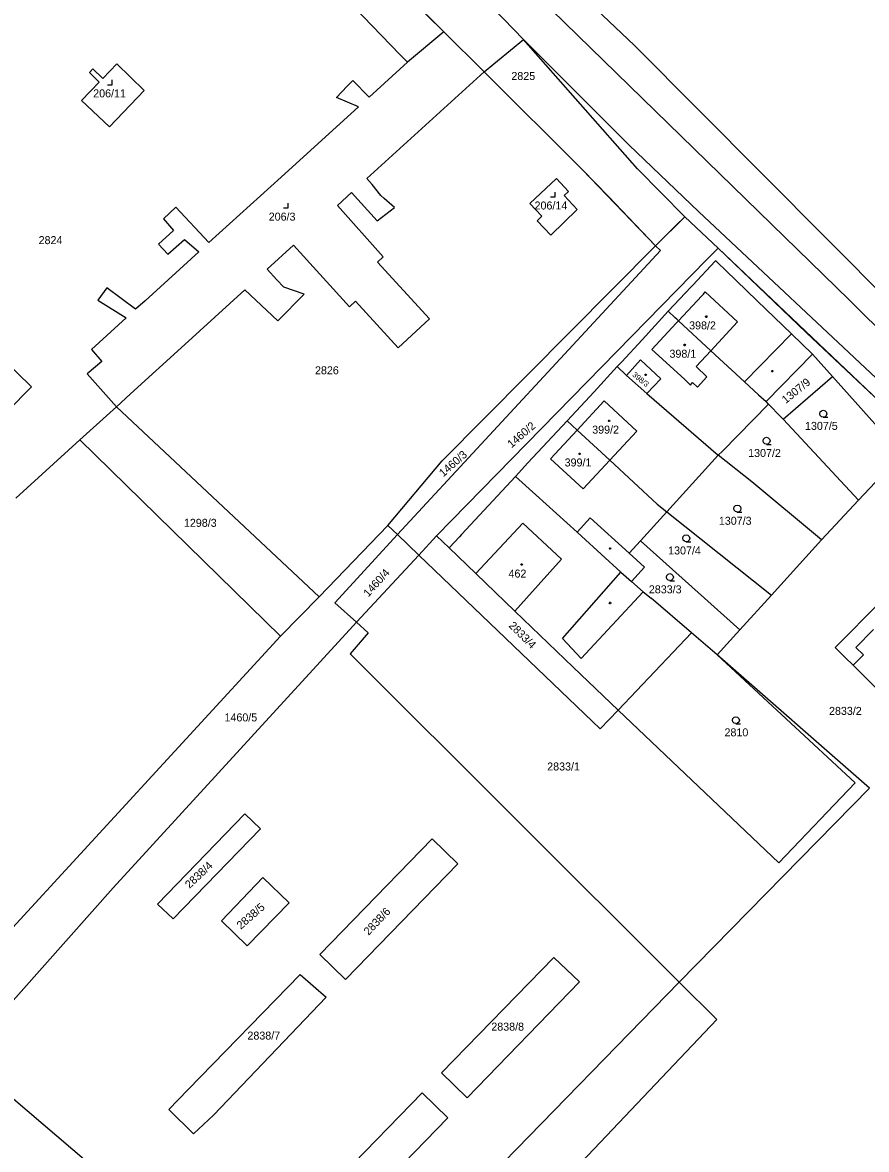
# Model space of a CAD drawing. Extents: x -580630 to -576196, y -1189024 to -1183567.
# Drawn here: x -577874.8 to -577695.4, y -1187048.7 to -1186809.3 of the extents above; entities that cross this region are included whole.
import ezdxf

# ---------------------------------------------------------------- set-up
doc = ezdxf.new("R2010")
doc.units = 0
for name, color, linetype in [('Vrstva 1', 7, 'Continuous'), ('Vrstva 18', 7, 'Continuous'), ('Vrstva 19', 7, 'Continuous'), ('Vrstva 25', 7, 'Continuous'), ('Vrstva 4', 7, 'Continuous'), ('Vrstva 63', 7, 'Continuous')]:
    doc.layers.add(name, color=color, linetype=linetype)

msp = doc.modelspace()

# ---------------------------------------------------------------- linework, layer by layer
at = {"layer": 'Vrstva 1'}
for p, q in [((-577782.94, -1186777.73), (-577744.75, -1186814.09)), ((-577800.81, -1186795.8), (-577785.23, -1186811.22)), ((-577768.28, -1186812.86), (-577782.75, -1186797.76)), ((-577807.36, -1186802.79), (-577794.61, -1186816.06)), ((-577785.23, -1186811.22), (-577792.94, -1186817.71)), ((-577785.23, -1186811.22), (-577776.66, -1186819.72)), ((-577773.84, -1186817.41), (-577768.28, -1186812.86)), ((-577744.05, -1186840.37), (-577768.28, -1186812.86)), ((-577794.61, -1186816.06), (-577792.94, -1186817.71)), ((-577744.75, -1186814.09), (-577644.5, -1186914.93)), ((-577854.75, -1186818.07), (-577857.71, -1186821.15)), ((-577848.88, -1186823.72), (-577854.75, -1186818.07)), ((-577792.94, -1186817.71), (-577801.12, -1186825.14)), ((-577776.66, -1186819.72), (-577774.63, -1186818.06)), ((-577774.63, -1186818.06), (-577773.84, -1186817.41)), ((-577859.82, -1186819.14), (-577860.55, -1186819.89)), ((-577860.55, -1186819.89), (-577858.49, -1186821.96)), ((-577857.71, -1186821.15), (-577859.82, -1186819.14)), ((-577801.58, -1186842.42), (-577776.66, -1186819.72)), ((-577755.77, -1186840.55), (-577776.66, -1186819.72)), ((-577858.49, -1186821.96), (-577862.22, -1186825.84)), ((-577808.07, -1186825.19), (-577805.79, -1186822.78)), ((-577805.79, -1186822.78), (-577804.55, -1186821.56)), ((-577804.55, -1186821.56), (-577801.12, -1186825.14)), ((-577856.29, -1186831.45), (-577848.88, -1186823.72)), ((-577803.35, -1186827.16), (-577808.07, -1186825.19)), ((-577862.22, -1186825.84), (-577856.29, -1186831.45)), ((-577803.35, -1186827.16), (-577819.81, -1186842.11)), ((-577819.81, -1186842.11), (-577835.15, -1186856.03)), ((-577800.48, -1186843.65), (-577801.58, -1186842.42)), ((-577766.94, -1186847.71), (-577761.3, -1186842.44)), ((-577761.3, -1186842.44), (-577758.76, -1186845.16)), ((-577750.21, -1186846.26), (-577755.77, -1186840.55)), ((-577734, -1186850.52), (-577744.05, -1186840.37)), ((-577798.63, -1186846.02), (-577800.48, -1186843.65)), ((-577807.85, -1186848.13), (-577804.85, -1186845.4)), ((-577804.85, -1186845.4), (-577799.37, -1186851.42)), ((-577797.93, -1186846.68), (-577798.63, -1186846.02)), ((-577795.74, -1186848.59), (-577797.93, -1186846.68)), ((-577758.76, -1186845.16), (-577759.62, -1186846.03)), ((-577759.62, -1186846.03), (-577756.86, -1186848.97)), ((-577740.21, -1186856.7), (-577750.21, -1186846.26)), ((-577842.17, -1186848.48), (-577844.84, -1186851)), ((-577835.15, -1186856.03), (-577842.17, -1186848.48)), ((-577798.1, -1186859.02), (-577807.85, -1186848.13)), ((-577799.37, -1186851.42), (-577795.74, -1186848.59)), ((-577764.38, -1186850.44), (-577766.94, -1186847.71)), ((-577756.86, -1186848.97), (-577762.49, -1186854.48)), ((-577844.84, -1186851), (-577842.65, -1186853.47)), ((-577765.42, -1186851.41), (-577764.38, -1186850.44)), ((-577762.49, -1186854.48), (-577765.42, -1186851.41)), ((-577735.9, -1186852.41), (-577734, -1186850.52)), ((-577734, -1186850.52), (-577726.95, -1186857.21)), ((-577842.65, -1186853.47), (-577845.86, -1186856.35)), ((-577740.21, -1186856.7), (-577736.61, -1186853.12)), ((-577736.61, -1186853.12), (-577735.9, -1186852.41)), ((-577845.86, -1186856.35), (-577843.91, -1186858.47)), ((-577843.91, -1186858.47), (-577840.36, -1186855.34)), ((-577840.36, -1186855.34), (-577837.27, -1186857.96)), ((-577822.77, -1186861.7), (-577817.15, -1186856.59)), ((-577817.15, -1186856.59), (-577805.3, -1186869.66)), ((-577785.58, -1186902.38), (-577740.21, -1186856.7)), ((-577739.17, -1186857.68), (-577740.21, -1186856.7)), ((-577837.27, -1186857.96), (-577848.7, -1186868.38)), ((-577799.34, -1186860.18), (-577798.1, -1186859.02)), ((-577795.04, -1186918.08), (-577739.17, -1186857.68)), ((-577729.3, -1186859.62), (-577728.55, -1186858.85)), ((-577728.55, -1186858.85), (-577726.95, -1186857.21)), ((-577726.95, -1186857.21), (-577691.26, -1186891.06)), ((-577788.27, -1186872.25), (-577799.34, -1186860.18)), ((-577786.79, -1186918.33), (-577729.3, -1186859.62)), ((-577727.54, -1186859.97), (-577732.3, -1186865.05)), ((-577727.45, -1186859.87), (-577727.54, -1186859.97)), ((-577727.08, -1186860.23), (-577727.45, -1186859.87)), ((-577725.29, -1186861.95), (-577727.08, -1186860.23)), ((-577820.71, -1186863.94), (-577822.77, -1186861.7)), ((-577819.25, -1186865.53), (-577820.71, -1186863.94)), ((-577718.61, -1186868.4), (-577725.29, -1186861.95)), ((-577856.87, -1186865.61), (-577858.79, -1186868.26)), ((-577850.77, -1186870.2), (-577856.87, -1186865.61)), ((-577840.3, -1186877.65), (-577827.54, -1186866.04)), ((-577827.54, -1186866.04), (-577820.51, -1186872.68)), ((-577814.9, -1186866.97), (-577819.25, -1186865.53)), ((-577732.65, -1186865.42), (-577737.52, -1186870.62)), ((-577732.3, -1186865.05), (-577732.65, -1186865.42)), ((-577858.79, -1186868.26), (-577852.77, -1186872.04)), ((-577848.7, -1186868.38), (-577850.77, -1186870.2)), ((-577820.51, -1186872.68), (-577814.9, -1186866.97)), ((-577805.3, -1186869.66), (-577803.99, -1186868.47)), ((-577803.99, -1186868.47), (-577794.9, -1186878.4)), ((-577711.33, -1186875.42), (-577718.61, -1186868.4)), ((-577737.52, -1186870.62), (-577743.11, -1186876.67)), ((-577736.06, -1186871.98), (-577737.52, -1186870.62)), ((-577852.77, -1186872.04), (-577860.12, -1186878.72)), ((-577794.9, -1186878.4), (-577788.27, -1186872.25)), ((-577735.69, -1186872.32), (-577736.06, -1186871.98)), ((-577735.36, -1186872.63), (-577735.69, -1186872.32)), ((-577728.47, -1186879), (-577735.36, -1186872.63)), ((-577711.33, -1186875.42), (-577706.86, -1186879.71)), ((-577851.82, -1186888.13), (-577840.3, -1186877.65)), ((-577743.11, -1186876.67), (-577747.42, -1186881.36)), ((-577872.83, -1186886.7), (-577879.18, -1186880.49)), ((-577860.12, -1186878.72), (-577857.88, -1186881.26)), ((-577728.47, -1186879), (-577721.32, -1186885.59)), ((-577706.86, -1186879.71), (-577716.71, -1186889.82)), ((-577702.59, -1186884.51), (-577706.86, -1186879.71)), ((-577857.88, -1186881.26), (-577861.01, -1186883.91)), ((-577753.25, -1186887.71), (-577748.4, -1186882.35)), ((-577747.42, -1186881.36), (-577748.4, -1186882.35)), ((-577748.4, -1186882.35), (-577746.43, -1186884.23)), ((-577746.43, -1186884.23), (-577743.44, -1186880.97)), ((-577743.44, -1186880.97), (-577739.12, -1186884.97)), ((-577861.01, -1186883.91), (-577854.82, -1186890.94)), ((-577746.43, -1186884.23), (-577742.06, -1186888.08)), ((-577739.12, -1186884.97), (-577742.06, -1186888.08)), ((-577713.14, -1186893.56), (-577702.59, -1186884.51)), ((-577687.91, -1186901.01), (-577702.59, -1186884.51)), ((-577877.99, -1186891.84), (-577872.83, -1186886.7)), ((-577758.99, -1186893.87), (-577753.25, -1186887.71)), ((-577721.32, -1186885.59), (-577718.32, -1186888.35)), ((-577854.82, -1186890.94), (-577851.82, -1186888.13)), ((-577742.06, -1186888.08), (-577726.94, -1186901.16)), ((-577726.01, -1186900.35), (-577716.22, -1186890.33)), ((-577718.32, -1186888.35), (-577716.71, -1186889.82)), ((-577716.22, -1186890.33), (-577716.71, -1186889.82)), ((-577713.63, -1186893.03), (-577716.22, -1186890.33)), ((-577862.56, -1186897.96), (-577854.82, -1186890.94)), ((-577854.82, -1186890.94), (-577811.71, -1186931.31)), ((-577758.99, -1186893.87), (-577767.35, -1186902.85)), ((-577756.88, -1186895.85), (-577758.99, -1186893.87)), ((-577713.14, -1186893.56), (-577713.63, -1186893.03)), ((-577697.12, -1186910.75), (-577713.14, -1186893.56)), ((-577756.88, -1186895.85), (-577749.94, -1186902.26)), ((-577876.19, -1186910.33), (-577862.56, -1186897.96)), ((-577862.56, -1186897.96), (-577819.93, -1186939.63)), ((-577749.94, -1186902.26), (-577739.91, -1186911.59)), ((-577726.94, -1186901.16), (-577737.84, -1186913.24)), ((-577726.94, -1186901.16), (-577726.01, -1186900.35)), ((-577719.74, -1186906.86), (-577726.94, -1186901.16)), ((-577687.91, -1186901.01), (-577697.12, -1186910.75)), ((-577797.1, -1186916.11), (-577785.58, -1186902.38)), ((-577767.35, -1186902.85), (-577770, -1186905.7)), ((-577770, -1186905.7), (-577781.49, -1186918.08)), ((-577770, -1186905.7), (-577765.67, -1186909.62)), ((-577704.93, -1186919.16), (-577719.74, -1186906.86)), ((-577765.67, -1186909.62), (-577756.87, -1186917.57)), ((-577739.91, -1186911.59), (-577737.84, -1186913.24)), ((-577697.12, -1186910.75), (-577704.93, -1186919.16)), ((-577737.84, -1186913.24), (-577743.4, -1186919.37)), ((-577737.84, -1186913.24), (-577715.61, -1186930.91)), ((-577811.71, -1186931.31), (-577797.1, -1186916.11)), ((-577795.04, -1186918.08), (-577797.1, -1186916.11)), ((-577808.38, -1186932.58), (-577795.04, -1186918.08)), ((-577795.04, -1186918.08), (-577790.55, -1186922.43)), ((-577786.79, -1186918.33), (-577790.55, -1186922.43)), ((-577784.11, -1186920.9), (-577786.79, -1186918.33)), ((-577781.9, -1186918.52), (-577784.11, -1186920.9)), ((-577781.49, -1186918.08), (-577781.9, -1186918.52)), ((-577756.87, -1186917.57), (-577755.96, -1186918.41)), ((-577755.96, -1186918.41), (-577747.59, -1186926.06)), ((-577778.41, -1186926.37), (-577784.11, -1186920.9)), ((-577743.4, -1186919.37), (-577745.82, -1186922.04)), ((-577743.4, -1186919.37), (-577722.32, -1186938.32)), ((-577704.93, -1186919.16), (-577715.61, -1186930.91)), ((-577790.55, -1186922.43), (-577803.78, -1186936.69)), ((-577790.55, -1186922.43), (-577752, -1186959.36)), ((-577745.82, -1186922.04), (-577742.56, -1186924.98)), ((-577747.59, -1186926.06), (-577745.35, -1186928.07)), ((-577742.56, -1186924.98), (-577745.35, -1186928.07)), ((-577770.12, -1186934.33), (-577778.41, -1186926.37)), ((-577745.35, -1186928.07), (-577742.83, -1186930.23)), ((-577742.83, -1186930.23), (-577741.19, -1186931.61)), ((-577715.61, -1186930.91), (-577722.32, -1186938.32)), ((-577819.93, -1186939.63), (-577811.71, -1186931.31)), ((-577803.78, -1186936.69), (-577808.38, -1186932.58)), ((-577732.59, -1186938.96), (-577741.19, -1186931.61)), ((-577702.03, -1186942.08), (-577692.35, -1186932.31)), ((-577757.72, -1186946.23), (-577770.12, -1186934.33)), ((-577855.48, -1186993.12), (-577803.78, -1186936.69)), ((-577803.78, -1186936.69), (-577801.29, -1186938.93)), ((-577913.56, -1187041.44), (-577819.93, -1186939.63)), ((-577801.29, -1186938.93), (-577805.16, -1186943.44)), ((-577748.21, -1186955.36), (-577732.59, -1186938.96)), ((-577727.13, -1186943.63), (-577732.59, -1186938.96)), ((-577722.32, -1186938.32), (-577727.13, -1186943.63)), ((-577699.9, -1186944.19), (-577702.03, -1186942.08)), ((-577805.16, -1186943.44), (-577735.21, -1187013.14)), ((-577694.74, -1186971.96), (-577727.13, -1186943.63)), ((-577697.79, -1186970.78), (-577727.13, -1186943.63)), ((-577698.24, -1186945.83), (-577699.9, -1186944.19)), ((-577748.21, -1186955.36), (-577757.72, -1186946.23)), ((-577692.83, -1186951.19), (-577698.24, -1186945.83)), ((-577752, -1186959.36), (-577748.21, -1186955.36)), ((-577748.21, -1186955.36), (-577714.01, -1186987.81)), ((-577714.01, -1186987.81), (-577697.79, -1186970.78)), ((-577735.21, -1187013.14), (-577694.74, -1186971.96)), ((-577846.07, -1186996.58), (-577827.55, -1186977.43)), ((-577827.55, -1186977.43), (-577824.21, -1186980.6)), ((-577824.21, -1186980.6), (-577842.76, -1186999.73)), ((-577811.59, -1187007.3), (-577787.69, -1186982.69)), ((-577787.69, -1186982.69), (-577782.23, -1186988.06)), ((-577782.23, -1186988.06), (-577806.12, -1187012.61)), ((-577926.93, -1187073.35), (-577855.48, -1186993.12)), ((-577832.48, -1187000.11), (-577823.71, -1186990.93)), ((-577823.71, -1186990.93), (-577818.08, -1186996.29)), ((-577842.76, -1186999.73), (-577846.07, -1186996.58)), ((-577818.08, -1186996.29), (-577827, -1187005.42)), ((-577827, -1187005.42), (-577832.48, -1187000.11)), ((-577806.12, -1187012.61), (-577811.59, -1187007.3)), ((-577785.73, -1187032.43), (-577761.85, -1187007.9)), ((-577761.85, -1187007.9), (-577756.39, -1187013.13)), ((-577839.62, -1187036.05), (-577815.73, -1187011.54)), ((-577815.73, -1187011.54), (-577810.21, -1187016.36)), ((-577823.41, -1187103.68), (-577735.21, -1187013.14)), ((-577756.39, -1187013.13), (-577780.3, -1187037.72)), ((-577735.21, -1187013.14), (-577727.19, -1187021.13)), ((-577810.21, -1187016.36), (-577834.17, -1187041.4)), ((-577727.19, -1187021.13), (-577866, -1187166.92)), ((-577882.65, -1187032.88), (-577841.16, -1187068.17)), ((-577780.3, -1187037.72), (-577785.73, -1187032.43)), ((-577843.65, -1187040.21), (-577839.62, -1187036.05)), ((-577789.84, -1187036.7), (-577813.8, -1187061.25)), ((-577784.4, -1187042.01), (-577789.84, -1187036.7)), ((-577838.43, -1187045.4), (-577843.65, -1187040.21)), ((-577834.17, -1187041.4), (-577838.43, -1187045.4)), ((-577808.39, -1187066.6), (-577784.4, -1187042.01))]:
    msp.add_line(p, q, dxfattribs=at)
at = {"layer": 'Vrstva 25'}
for points in [[(-577856.72, -1186822.47), (-577855.72, -1186822.47), (-577855.72, -1186821.47)], [(-577762.57, -1186846.29), (-577761.57, -1186846.29), (-577761.57, -1186845.29)], [(-577819.32, -1186848.66), (-577818.32, -1186848.66), (-577818.32, -1186847.66)], [(-577704.57, -1186893.12), (-577704.95, -1186893.02), (-577705.22, -1186892.75), (-577705.32, -1186892.38), (-577705.22, -1186892.01), (-577704.95, -1186891.74), (-577704.58, -1186891.64), (-577704.21, -1186891.74), (-577703.94, -1186892.01), (-577703.84, -1186892.39), (-577703.94, -1186892.77), (-577704.21, -1186893.04), (-577704.59, -1186893.14), (-577703.59, -1186893.14)], [(-577716.63, -1186898.88), (-577717.01, -1186898.78), (-577717.28, -1186898.51), (-577717.38, -1186898.14), (-577717.28, -1186897.77), (-577717.01, -1186897.5), (-577716.64, -1186897.4), (-577716.27, -1186897.5), (-577716, -1186897.77), (-577715.9, -1186898.15), (-577716, -1186898.53), (-577716.27, -1186898.8), (-577716.65, -1186898.9), (-577715.65, -1186898.9)], [(-577722.84, -1186913.28), (-577723.22, -1186913.18), (-577723.49, -1186912.91), (-577723.59, -1186912.54), (-577723.49, -1186912.17), (-577723.22, -1186911.9), (-577722.85, -1186911.8), (-577722.48, -1186911.9), (-577722.21, -1186912.17), (-577722.11, -1186912.55), (-577722.21, -1186912.93), (-577722.48, -1186913.2), (-577722.86, -1186913.3), (-577721.86, -1186913.3)], [(-577733.71, -1186919.59), (-577734.09, -1186919.49), (-577734.36, -1186919.22), (-577734.46, -1186918.85), (-577734.36, -1186918.48), (-577734.09, -1186918.21), (-577733.72, -1186918.11), (-577733.35, -1186918.21), (-577733.08, -1186918.48), (-577732.98, -1186918.86), (-577733.08, -1186919.24), (-577733.35, -1186919.51), (-577733.73, -1186919.61), (-577732.73, -1186919.61)], [(-577737.17, -1186927.85), (-577737.55, -1186927.75), (-577737.82, -1186927.48), (-577737.92, -1186927.11), (-577737.82, -1186926.74), (-577737.55, -1186926.47), (-577737.18, -1186926.37), (-577736.81, -1186926.47), (-577736.54, -1186926.74), (-577736.44, -1186927.12), (-577736.54, -1186927.5), (-577736.81, -1186927.77), (-577737.19, -1186927.87), (-577736.19, -1186927.87)], [(-577723.15, -1186958.24), (-577723.53, -1186958.14), (-577723.8, -1186957.87), (-577723.9, -1186957.5), (-577723.8, -1186957.13), (-577723.53, -1186956.86), (-577723.16, -1186956.76), (-577722.79, -1186956.86), (-577722.52, -1186957.13), (-577722.42, -1186957.51), (-577722.52, -1186957.89), (-577722.79, -1186958.16), (-577723.17, -1186958.26), (-577722.17, -1186958.26)]]:
    msp.add_lwpolyline(points, dxfattribs=at)
for points in [[(-577729.38, -1186871.62), (-577729.29, -1186871.77), (-577729.38, -1186871.92), (-577729.56, -1186871.92), (-577729.65, -1186871.77), (-577729.56, -1186871.62)], [(-577733.98, -1186877.64), (-577733.89, -1186877.79), (-577733.98, -1186877.94), (-577734.16, -1186877.94), (-577734.25, -1186877.79), (-577734.16, -1186877.64)], [(-577742.24, -1186883.95), (-577742.15, -1186884.1), (-577742.24, -1186884.25), (-577742.42, -1186884.25), (-577742.51, -1186884.1), (-577742.42, -1186883.95)], [(-577715.35, -1186883.2), (-577715.26, -1186883.35), (-577715.35, -1186883.5), (-577715.53, -1186883.5), (-577715.62, -1186883.35), (-577715.53, -1186883.2)], [(-577750.01, -1186893.77), (-577749.92, -1186893.92), (-577750.01, -1186894.07), (-577750.19, -1186894.07), (-577750.28, -1186893.92), (-577750.19, -1186893.77)], [(-577756.29, -1186900.74), (-577756.2, -1186900.89), (-577756.29, -1186901.04), (-577756.47, -1186901.04), (-577756.56, -1186900.89), (-577756.47, -1186900.74)], [(-577749.79, -1186920.85), (-577749.7, -1186921), (-577749.79, -1186921.15), (-577749.97, -1186921.15), (-577750.06, -1186921), (-577749.97, -1186920.85)], [(-577768.6, -1186924.26), (-577768.51, -1186924.41), (-577768.6, -1186924.56), (-577768.78, -1186924.56), (-577768.87, -1186924.41), (-577768.78, -1186924.26)], [(-577749.79, -1186932.45), (-577749.7, -1186932.6), (-577749.79, -1186932.75), (-577749.97, -1186932.75), (-577750.06, -1186932.6), (-577749.97, -1186932.45)]]:
    msp.add_lwpolyline(points, close=True, dxfattribs=at)
at = {"layer": 'Vrstva 4'}
for p, q in [((-577786.85, -1186782.68), (-577699.08, -1186868.19)), ((-577745.91, -1186835.26), (-577768.28, -1186812.86)), ((-577731.02, -1186849.51), (-577745.91, -1186835.26)), ((-577691.16, -1186886.86), (-577731.02, -1186849.51)), ((-577735.36, -1186872.63), (-577730.36, -1186867.33)), ((-577730.36, -1186867.33), (-577730.01, -1186866.96)), ((-577730.01, -1186866.96), (-577729.69, -1186866.52)), ((-577722.83, -1186872.88), (-577729.69, -1186866.52)), ((-577699.08, -1186868.19), (-577662.35, -1186904.79)), ((-577741, -1186878.71), (-577735.83, -1186873.14)), ((-577735.83, -1186873.14), (-577735.48, -1186872.76)), ((-577735.48, -1186872.76), (-577735.36, -1186872.63)), ((-577722.83, -1186872.88), (-577728.47, -1186879)), ((-577721.32, -1186885.59), (-577711.33, -1186875.42)), ((-577734.11, -1186885.06), (-577741, -1186878.71)), ((-577728.47, -1186879), (-577731.62, -1186882.37)), ((-577729.3, -1186884.53), (-577731.62, -1186882.37)), ((-577734.11, -1186885.06), (-577732.83, -1186886.3)), ((-577731.34, -1186886.72), (-577729.3, -1186884.53)), ((-577732.83, -1186886.3), (-577732.35, -1186885.78)), ((-577732.35, -1186885.78), (-577731.34, -1186886.72)), ((-577756.88, -1186895.85), (-577751.17, -1186889.66)), ((-577751.17, -1186889.66), (-577744.23, -1186896.1)), ((-577762.53, -1186901.95), (-577756.88, -1186895.85)), ((-577744.23, -1186896.1), (-577749.94, -1186902.26)), ((-577762.53, -1186901.95), (-577755.6, -1186908.36)), ((-577755.6, -1186908.36), (-577749.94, -1186902.26)), ((-577778.41, -1186926.37), (-577768.43, -1186915.65)), ((-577760.19, -1186923.31), (-577768.43, -1186915.65)), ((-577754.12, -1186914.52), (-577756.87, -1186917.57)), ((-577754.12, -1186914.52), (-577745.82, -1186922.04)), ((-577760.19, -1186923.31), (-577770.12, -1186934.33)), ((-577760.01, -1186940.14), (-577747.59, -1186926.06)), ((-577756.02, -1186944.4), (-577742.83, -1186930.23)), ((-577697.66, -1186942.04), (-577693.94, -1186938.22)), ((-577756.02, -1186944.4), (-577760.01, -1186940.14)), ((-577696.07, -1186943.59), (-577697.66, -1186942.04)), ((-577698.24, -1186945.83), (-577696.07, -1186943.59))]:
    msp.add_line(p, q, dxfattribs=at)
at = {"layer": 'Vrstva 63'}
for p, q in [((-577809.27, -1186787.5), (-577785.23, -1186811.22)), ((-577785.23, -1186811.22), (-577776.66, -1186819.72)), ((-577776.66, -1186819.72), (-577755.77, -1186840.55)), ((-577755.77, -1186840.55), (-577740.21, -1186856.7)), ((-577740.21, -1186856.7), (-577734, -1186850.52)), ((-577734, -1186850.52), (-577726.95, -1186857.21)), ((-577726.95, -1186857.21), (-577708.217, -1186875.104)), ((-577708.217, -1186875.104), (-577691.26, -1186891.06)), ((-577694.74, -1186971.96), (-577735.21, -1187013.14)), ((-577735.21, -1187013.14), (-577727.19, -1187021.13)), ((-577727.19, -1187021.13), (-577796.595, -1187094.025))]:
    msp.add_line(p, q, dxfattribs=at)

# ---------------------------------------------------------------- texts
at = {"layer": 'Vrstva 18'}
for s, p in [('2825', (-577770.874, -1186821.48)), ('2824', (-577871.347, -1186856.35)), ('2826', (-577812.607, -1186884.01)), ('1307/5', (-577708.465, -1186895.82)), ('1307/2', (-577720.552, -1186901.58)), ('1307/3', (-577726.775, -1186915.98)), ('1298/3', (-577840.462, -1186916.42)), ('1307/4', (-577737.558, -1186922.29)), ('2833/3', (-577741.654, -1186930.55)), ('2833/2', (-577703.361, -1186956.38)), ('1460/5', (-577831.838, -1186957.76)), ('2810', (-577725.573, -1186960.94)), ('2833/1', (-577763.259, -1186968.19)), ('2838/8', (-577775.137, -1187023.47)), ('2838/7', (-577826.966, -1187025.37))]:
    msp.add_text(s, height=1.7, dxfattribs=at).set_placement(p)
for s, rotation, p in [('1307/9', 38.78924, (-577712.559, -1186890.341)), ('1460/2', 40.68, (-577770.839, -1186899.756)), ('1460/3', 41.42485, (-577785.335, -1186905.913)), ('1460/4', 48.01386, (-577801.253, -1186931.445)), ('2833/4', 315.01219, (-577771.57, -1186937.542)), ('2838/4', 43.20102, (-577839.271, -1186993.369)), ('2838/5', 41.02378, (-577828.357, -1187002.037)), ('2838/6', 46.40958, (-577801.21, -1187003.321))]:
    msp.add_text(s, height=1.7, rotation=rotation, dxfattribs=at).set_placement(p)
at = {"layer": 'Vrstva 19'}
for s, p in [('206/11', (-577859.747, -1186825.17)), ('206/14', (-577765.945, -1186848.99)), ('206/3', (-577822.441, -1186851.36)), ('398/2', (-577733.091, -1186874.47)), ('398/1', (-577737.269, -1186880.49)), ('399/2', (-577753.694, -1186896.62)), ('399/1', (-577759.552, -1186903.59)), ('462', (-577771.478, -1186927.2))]:
    msp.add_text(s, height=1.7, dxfattribs=at).set_placement(p)
msp.add_text('398/3', height=1.14, rotation=320.68448, dxfattribs=at).set_placement((-577745.267, -1186884.291))

doc.saveas('drawing.dxf')
